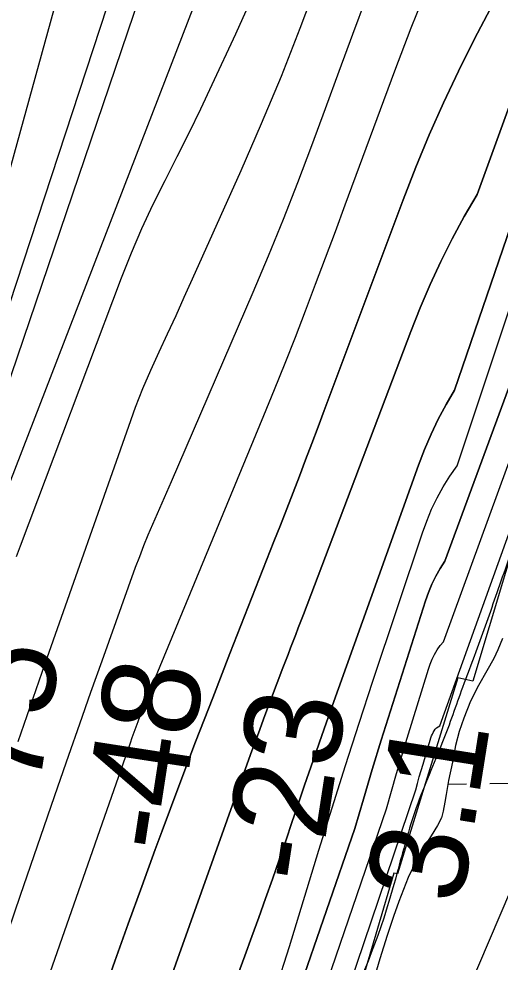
# Model space of a CAD drawing. Extents: x 3807117 to 3845308, y 337856 to 363736.
# Drawn here: x 3833182 to 3833513, y 344120 to 344768 of the extents above; entities that cross this region are included whole.
import ezdxf

# ---------------------------------------------------------------- set-up
doc = ezdxf.new("R2010")
doc.units = 0
for name, color, linetype in [('V-RIVR-EDGE', 7, 'Continuous'), ('V-RIVR-RANG', 7, 'Continuous'), ('V-RRAP-RVMT', 7, 'Continuous'), ('V-TOPO-DPTH', 7, 'Continuous'), ('V-TOPO-MAJR', 7, 'Continuous'), ('V-TOPO-MINR', 7, 'Continuous'), ('V-TOPO-WATR', 7, 'Continuous'), ('V-WETL-SWMP', 7, 'Continuous')]:
    doc.layers.add(name, color=color, linetype=linetype)

msp = doc.modelspace()

# ---------------------------------------------------------------- linework, layer by layer
at = {"layer": 'V-RIVR-EDGE'}
msp.add_spline([(3833993.63, 346073.15), (3834014.82, 346049.13), (3834027.93, 346045.03), (3834044.2, 346044.54), (3834056.42, 346046.77), (3834063.2, 346046.75), (3834065.46, 346045.39), (3834066.76, 346025.04), (3834070.78, 346004.68), (3834083.34, 345964.41), (3834083.78, 345960.79), (3834080.16, 345959.89), (3834071.58, 345963.98), (3834066.61, 345963.09), (3834057.1, 345958.14), (3834056.17, 345945.94), (3834053.89, 345939.61), (3834045.29, 345936.01), (3834032.17, 345933.79), (3834020.87, 345934.27), (3834010.46, 345930.67), (3833991.44, 345919.42), (3833968.34, 345903.65), (3833937.09, 345880.21), (3833918.03, 345855.85), (3833899.87, 345825.6), (3833887.57, 345788.55), (3833879.36, 345756.47), (3833874.27, 345710.36), (3833869.21, 345675.1), (3833852.34, 345618.62), (3833845.48, 345588.35), (3833842.69, 345557.15), (3833837.61, 345515.12), (3833834.32, 345463.13), (3833833.31, 345422.89), (3833835.49, 345389.87), (3833826.75, 345327.5), (3833812.58, 345266.04), (3833811.6, 345236.2), (3833805.63, 345198.23), (3833800.11, 345162.07), (3833798.68, 345131.78), (3833801.81, 345114.59), (3833810.79, 345092.41), (3833826.56, 345068.41), (3833838.72, 345048.94), (3833853.17, 345041.22), (3833864.45, 345032.14), (3833872.11, 345019.46), (3833872.08, 345008.16), (3833866.05, 344947.59), (3833859.08, 344872.55), (3833858.17, 344868.03), (3833853.65, 344868.04), (3833833.32, 344878.03), (3833815.73, 344894.81), (3833804.91, 344906.14), (3833797.68, 344908.87), (3833783.21, 344908.45), (3833736.6, 344893.2), (3833706.24, 344865.69), (3833687.65, 344845.39), (3833676.3, 344827.33), (3833665.38, 344800.68), (3833650.83, 344767.71), (3833632.62, 344715.75), (3833615.31, 344663.8), (3833598.93, 344623.14), (3833579.38, 344582.5), (3833566.62, 344539.57), (3833556.59, 344505.69), (3833525.62, 344416.69), (3833510.59, 344373.77), (3833496.02, 344333.11), (3833486.92, 344308.72), (3833473.26, 344271.22), (3833455.06, 344226.05), (3833441.84, 344180.87), (3833432.72, 344150.15), (3833396.31, 344055.73), (3833377.19, 344001.07), (3833358.09, 343958.61), (3833345.37, 343934.23), (3833328.05, 343879.56), (3833312.99, 343821.72), (3833296.6, 343775.64), (3833286.11, 343739.5), (3833276.03, 343687.07), (3833267.36, 343654.99), (3833255.05, 343614.32), (3833253.24, 343609.33)], degree=3, dxfattribs=at)
at = {"layer": 'V-RRAP-RVMT'}
for p, q in [((3833534.42, 344447.64), (3833494.04, 344313.06)), ((3833483.68, 344315.31), (3833442.17, 344180.65)), ((3833494.04, 344313.06), (3833483.68, 344315.31)), ((3833439.78, 344181.06), (3833400.57, 344049.13)), ((3833442.17, 344180.65), (3833439.78, 344181.06))]:
    msp.add_line(p, q, dxfattribs=at)
at = {"layer": 'V-TOPO-DPTH'}
for points in [[(3833630.63, 345014.55), (3833496.97, 344647.56), (3833488.19, 344632.52), (3833479.82, 344617.21), (3833472.06, 344601.58), (3833464.66, 344585.79), (3833457.82, 344569.74), (3833451.35, 344553.54), (3833377.45, 344358.79), (3833375.71, 344354.21), (3833373.95, 344349.63), (3833372.19, 344345.05), (3833370.41, 344340.48), (3833368.64, 344335.91), (3833366.88, 344331.33), (3833365.13, 344326.75), (3833363.39, 344322.17), (3833351.02, 344289.49), (3833346.47, 344277.36), (3833341.97, 344265.21), (3833337.54, 344253.03), (3833333.17, 344240.83), (3833281.5, 344095.44)], [(3833281.5, 344095.44), (3833333.17, 344240.83), (3833337.54, 344253.03), (3833341.97, 344265.21), (3833346.47, 344277.36), (3833351.02, 344289.49), (3833363.39, 344322.17), (3833365.13, 344326.75), (3833366.88, 344331.33), (3833368.64, 344335.91), (3833370.41, 344340.48), (3833372.19, 344345.05), (3833373.95, 344349.63), (3833375.71, 344354.21), (3833377.45, 344358.79), (3833451.35, 344553.54), (3833457.82, 344569.74), (3833464.66, 344585.79), (3833472.06, 344601.58), (3833479.82, 344617.21), (3833488.19, 344632.52), (3833496.97, 344647.56), (3833630.63, 345014.55)], [(3833641.2, 345004.31), (3833528.64, 344650.91), (3833481.49, 344513.01), (3833475.6, 344503.21), (3833470.3, 344493.06), (3833465.34, 344482.75), (3833460.88, 344472.22), (3833456.75, 344461.53), (3833396.19, 344292.71), (3833390.13, 344275.66), (3833384.14, 344258.59), (3833378.25, 344241.48), (3833372.42, 344224.35), (3833369.8, 344216.57), (3833365.3, 344203.33), (3833360.74, 344190.1), (3833356.11, 344176.9), (3833351.42, 344163.72), (3833346.69, 344150.56), (3833341.95, 344137.39), (3833337.2, 344124.24), (3833332.43, 344111.08)], [(3833332.43, 344111.08), (3833337.2, 344124.24), (3833341.95, 344137.39), (3833346.69, 344150.56), (3833351.42, 344163.72), (3833356.11, 344176.9), (3833360.74, 344190.1), (3833365.3, 344203.33), (3833369.8, 344216.57), (3833372.42, 344224.35), (3833378.25, 344241.48), (3833384.14, 344258.59), (3833390.13, 344275.66), (3833396.19, 344292.71), (3833456.75, 344461.53), (3833460.88, 344472.22), (3833465.34, 344482.75), (3833470.3, 344493.06), (3833475.6, 344503.21), (3833481.49, 344513.01), (3833528.64, 344650.91), (3833641.2, 345004.31)], [(3833197.92, 343608.5), (3833199.25, 343612.47), (3833212.54, 343649.95), (3833226.73, 343687.09), (3833241.54, 343724.01), (3833256.88, 343760.72), (3833412.87, 344211.65), (3833418.77, 344231.94), (3833424.8, 344252.2), (3833431.01, 344272.41), (3833437.35, 344292.57), (3833461.53, 344368.26), (3833463.59, 344374.01), (3833465.89, 344379.64), (3833468.56, 344385.11), (3833471.48, 344390.47), (3833474.86, 344395.5), (3833657.06, 344889.85)], [(3833657.06, 344889.85), (3833474.86, 344395.5), (3833471.48, 344390.47), (3833468.56, 344385.11), (3833465.89, 344379.64), (3833463.59, 344374.01), (3833461.53, 344368.26), (3833437.35, 344292.57), (3833431.01, 344272.41), (3833424.8, 344252.2), (3833418.77, 344231.94), (3833412.87, 344211.65), (3833256.88, 343760.72), (3833241.54, 343724.01), (3833226.73, 343687.09), (3833212.54, 343649.95), (3833199.25, 343612.47), (3833197.92, 343608.5)], [(3833241.74, 343609.16), (3833454.72, 344238.22), (3833455.93, 344242.7), (3833457.17, 344247.16), (3833458.45, 344251.62), (3833459.77, 344256.06), (3833465.25, 344274.16), (3833465.68, 344275.42), (3833466.18, 344276.64), (3833466.78, 344277.82), (3833467.44, 344278.97), (3833468.24, 344280), (3833469.13, 344280.91), (3833470.18, 344281.64), (3833471.33, 344282.24), (3833688.78, 344887.19)], [(3833506.15, 344775.51), (3833494.99, 344754.1), (3833484.15, 344732.52), (3833473.88, 344710.67), (3833464.04, 344688.64), (3833454.82, 344666.33), (3833446.03, 344643.85), (3833391.79, 344499.05), (3833387.54, 344487.77), (3833383.28, 344476.49), (3833378.99, 344465.23), (3833374.67, 344453.98), (3833370.33, 344442.73), (3833365.97, 344431.49), (3833361.59, 344420.27), (3833357.19, 344409.04), (3833326.89, 344332.03), (3833315.05, 344301.65), (3833303.32, 344271.23), (3833291.78, 344240.73), (3833280.35, 344210.2), (3833275.55, 344197.26), (3833266.17, 344171.75), (3833256.88, 344146.21), (3833247.73, 344120.62), (3833238.68, 344094.99)], [(3833238.68, 344094.99), (3833247.73, 344120.62), (3833256.88, 344146.21), (3833266.17, 344171.75), (3833275.55, 344197.26), (3833280.35, 344210.2), (3833291.78, 344240.73), (3833303.32, 344271.23), (3833315.05, 344301.65), (3833326.89, 344332.03), (3833357.19, 344409.04), (3833361.59, 344420.27), (3833365.97, 344431.49), (3833370.33, 344442.73), (3833374.67, 344453.98), (3833378.99, 344465.23), (3833383.28, 344476.49), (3833387.54, 344487.77), (3833391.79, 344499.05), (3833446.03, 344643.85), (3833454.82, 344666.33), (3833464.04, 344688.64), (3833473.88, 344710.67), (3833484.15, 344732.52), (3833494.99, 344754.1), (3833506.15, 344775.51)]]:
    msp.add_lwpolyline(points, dxfattribs=at)
at = {"layer": 'V-TOPO-MAJR'}
for points in [[(3832927.56, 343604.45), (3832927.66, 343604.82), (3832933.45, 343625.49), (3833008.69, 343896.96), (3833026.75, 343964.06), (3833044.15, 344031.32), (3833060.54, 344098.83), (3833076.27, 344166.51), (3833098.81, 344266.91), (3833102.65, 344284.54), (3833106.34, 344302.2), (3833109.8, 344319.9), (3833113.11, 344337.64), (3833315.5, 344933.25)], [(3833185.55, 344062.33), (3833258.43, 344270.61), (3833259.72, 344274.27), (3833261.02, 344277.92), (3833262.33, 344281.57), (3833263.66, 344285.22), (3833267.48, 344295.67), (3833267.98, 344297), (3833268.48, 344298.33), (3833269.01, 344299.65), (3833269.55, 344300.96), (3833270.1, 344302.27), (3833270.64, 344303.58), (3833271.19, 344304.89), (3833271.73, 344306.2), (3833350.29, 344495.59), (3833357.65, 344513.56), (3833364.9, 344531.56), (3833371.98, 344549.63), (3833378.95, 344567.74), (3833385.82, 344585.89), (3833392.66, 344604.06), (3833399.45, 344622.24), (3833406.21, 344640.43), (3833440.3, 344732.6), (3833451.6, 344762.09), (3833463.34, 344791.4)]]:
    msp.add_lwpolyline(points, dxfattribs=at)
at = {"layer": 'V-TOPO-MINR'}
for points in [[(3832857.18, 343603.4), (3832871.29, 343647.42), (3832899.09, 343733.62), (3832927.1, 343819.74), (3832955.43, 343905.76), (3832983.97, 343991.71), (3833028.08, 344123.76), (3833034.62, 344143.67), (3833041.02, 344163.61), (3833047.23, 344183.62), (3833053.3, 344203.67), (3833056.11, 344213.14), (3833060.46, 344228.54), (3833064.5, 344244.02), (3833068.11, 344259.6), (3833071.42, 344275.26), (3833076.32, 344300.21), (3833076.93, 344303.45), (3833077.51, 344306.7), (3833078.04, 344309.96), (3833078.53, 344313.22), (3833399.11, 345475.89)], [(3833281.14, 343609.75), (3833542.81, 344222.6), (3833545.01, 344227.54), (3833547.78, 344232.04), (3833575.64, 344292.26), (3833849.9, 345478.81)], [(3832892.2, 343603.92), (3832893.56, 343607.9), (3832911.37, 343661.09), (3832928.72, 343714.42), (3832945.77, 343767.86), (3832949.37, 343779.34), (3832967.78, 343838.65), (3832985.89, 343898.05), (3833003.57, 343957.59), (3833020.96, 344017.21), (3833031.9, 344055.24), (3833043.26, 344096.41), (3833054, 344137.74), (3833063.82, 344179.3), (3833073.03, 344221.01), (3833086.5, 344285.37), (3833088.45, 344295.03), (3833090.3, 344304.7), (3833092.02, 344314.4), (3833093.64, 344324.11), (3833468.24, 345464.24)], [(3833281.5, 344095.44), (3833333.17, 344240.83), (3833337.54, 344253.03), (3833341.97, 344265.21), (3833346.47, 344277.36), (3833351.02, 344289.49), (3833363.39, 344322.17), (3833365.13, 344326.75), (3833366.88, 344331.33), (3833368.64, 344335.91), (3833370.41, 344340.48), (3833372.19, 344345.05), (3833373.95, 344349.63), (3833375.71, 344354.21), (3833377.45, 344358.79), (3833451.35, 344553.54), (3833457.82, 344569.74), (3833464.66, 344585.79), (3833472.06, 344601.58), (3833479.82, 344617.21), (3833488.19, 344632.52), (3833496.97, 344647.56), (3833630.63, 345014.55)], [(3833332.43, 344111.08), (3833337.2, 344124.24), (3833341.95, 344137.39), (3833346.69, 344150.56), (3833351.42, 344163.72), (3833356.11, 344176.9), (3833360.74, 344190.1), (3833365.3, 344203.33), (3833369.8, 344216.57), (3833372.42, 344224.35), (3833378.25, 344241.48), (3833384.14, 344258.59), (3833390.13, 344275.66), (3833396.19, 344292.71), (3833456.75, 344461.53), (3833460.88, 344472.22), (3833465.34, 344482.75), (3833470.3, 344493.06), (3833475.6, 344503.21), (3833481.49, 344513.01), (3833528.64, 344650.91), (3833641.2, 345004.31)], [(3833358.59, 344101.16), (3833367.96, 344130.66), (3833388.13, 344196.81), (3833397.15, 344225.97), (3833406.33, 344255.08), (3833415.73, 344284.12), (3833425.29, 344313.1), (3833459.35, 344414.97), (3833462.35, 344423.14), (3833465.66, 344431.17), (3833469.44, 344439), (3833473.53, 344446.68), (3833478.17, 344454.01), (3833483.23, 344461), (3833657.1, 344983)], [(3832948.39, 343604.76), (3832985.52, 343740.44), (3833010.48, 343833.17), (3833034.92, 343926.03), (3833058.59, 344019.1), (3833081.73, 344112.3), (3833113.77, 344243.67), (3833120.35, 344271.32), (3833126.72, 344299.02), (3833132.78, 344326.79), (3833138.63, 344354.61), (3833347.97, 344895.76)], [(3833197.92, 343608.5), (3833199.25, 343612.47), (3833212.54, 343649.95), (3833226.73, 343687.09), (3833241.54, 343724.01), (3833256.88, 343760.72), (3833412.87, 344211.65), (3833418.77, 344231.94), (3833424.8, 344252.2), (3833431.01, 344272.41), (3833437.35, 344292.57), (3833461.53, 344368.26), (3833463.59, 344374.01), (3833465.89, 344379.64), (3833468.56, 344385.11), (3833471.48, 344390.47), (3833474.86, 344395.5), (3833657.06, 344889.85)], [(3833223.3, 343608.88), (3833434.64, 344225.28), (3833438.02, 344237.46), (3833441.49, 344249.6), (3833445.08, 344261.72), (3833448.76, 344273.8), (3833463.47, 344321.32), (3833464.68, 344324.76), (3833466.05, 344328.13), (3833467.67, 344331.39), (3833469.45, 344334.57), (3833471.55, 344337.5), (3833473.9, 344340.17), (3833668.71, 344873.67)], [(3833180.13, 344398.63), (3833182.82, 344406.12), (3833252.37, 344590.41), (3833259.15, 344607.45), (3833266.33, 344624.3), (3833274.1, 344640.89), (3833282.26, 344657.31), (3833290.62, 344673.64), (3833298.83, 344690.04), (3833306.83, 344706.55), (3833314.68, 344723.13), (3833330.94, 344758.05), (3833346.32, 344792.34)], [(3833181.23, 344271.55), (3833187.36, 344289.46), (3833193.56, 344307.34), (3833199.8, 344325.2), (3833257.23, 344488.4), (3833262, 344501.34), (3833267.04, 344514.16), (3833272.46, 344526.83), (3833278.15, 344539.39), (3833284, 344551.89), (3833289.8, 344564.4), (3833295.52, 344576.96), (3833301.2, 344589.53), (3833334.65, 344664.19), (3833348.72, 344696.53), (3833362.32, 344729.07), (3833375.2, 344761.89), (3833387.61, 344794.91)], [(3833166.12, 344117.34), (3833182.76, 344165.83), (3833208.46, 344240.49), (3833215.96, 344262.15), (3833223.52, 344283.78), (3833231.17, 344305.38), (3833238.88, 344326.96), (3833262, 344391.32), (3833264.79, 344398.82), (3833267.69, 344406.28), (3833270.75, 344413.68), (3833273.91, 344421.03), (3833277.15, 344428.36), (3833280.37, 344435.69), (3833283.57, 344443.04), (3833286.75, 344450.39), (3833342.8, 344580.4), (3833353.37, 344605.44), (3833363.68, 344630.59), (3833373.61, 344655.9), (3833383.27, 344681.3), (3833392.72, 344706.8), (3833402.14, 344732.3), (3833411.51, 344757.82), (3833420.86, 344783.35)], [(3833238.68, 344094.99), (3833247.73, 344120.62), (3833256.88, 344146.21), (3833266.17, 344171.75), (3833275.55, 344197.26), (3833280.35, 344210.2), (3833291.78, 344240.73), (3833303.32, 344271.23), (3833315.05, 344301.65), (3833326.89, 344332.03), (3833357.19, 344409.04), (3833361.59, 344420.27), (3833365.97, 344431.49), (3833370.33, 344442.73), (3833374.67, 344453.98), (3833378.99, 344465.23), (3833383.28, 344476.49), (3833387.54, 344487.77), (3833391.79, 344499.05), (3833446.03, 344643.85), (3833454.82, 344666.33), (3833464.04, 344688.64), (3833473.88, 344710.67), (3833484.15, 344732.52), (3833494.99, 344754.1), (3833506.15, 344775.51)]]:
    msp.add_lwpolyline(points, dxfattribs=at)
at = {"layer": 'V-TOPO-WATR'}
msp.add_lwpolyline([(3833241.74, 343609.16), (3833454.72, 344238.22), (3833455.93, 344242.7), (3833457.17, 344247.16), (3833458.45, 344251.62), (3833459.77, 344256.06), (3833465.25, 344274.16), (3833465.68, 344275.42), (3833466.18, 344276.64), (3833466.78, 344277.82), (3833467.44, 344278.97), (3833468.24, 344280), (3833469.13, 344280.91), (3833470.18, 344281.64), (3833471.33, 344282.24), (3833688.78, 344887.19)], dxfattribs=at)
at = {"layer": 'V-WETL-SWMP'}
for p, q in [((3833514.5, 344342.38), (3833511.23, 344334.49)), ((3833511.23, 344334.49), (3833508.61, 344328.58)), ((3833508.61, 344328.58), (3833503.63, 344320.16)), ((3833503.63, 344320.16), (3833497.99, 344310.04)), ((3833497.99, 344310.04), (3833492.49, 344299.26)), ((3833492.49, 344299.26), (3833487.91, 344287.69)), ((3833487.91, 344287.69), (3833484.64, 344278.49)), ((3833484.64, 344278.49), (3833482.16, 344268.76)), ((3833482.16, 344268.76), (3833479.95, 344257.33)), ((3833479.95, 344257.33), (3833477.21, 344244.71)), ((3833477.21, 344244.71), (3833475.78, 344235.12)), ((3833476.83, 344242.17), (3833489.74, 344242.36)), ((3833505.74, 344242.6), (3833537.73, 344243.08)), ((3833475.78, 344235.12), (3833474.73, 344229.73)), ((3833474.73, 344229.73), (3833473.69, 344223.56)), ((3833473.69, 344223.56), (3833472.39, 344218.96)), ((3833472.39, 344218.96), (3833469.63, 344213.7)), ((3833469.63, 344213.7), (3833465.44, 344206.73)), ((3833465.44, 344206.73), (3833461.38, 344200.55)), ((3833461.38, 344200.55), (3833455.48, 344190.29)), ((3833455.48, 344190.29), (3833449.59, 344178.07)), ((3833449.59, 344178.07), (3833443.05, 344161.64)), ((3833443.05, 344161.64), (3833439.38, 344151.12)), ((3833439.38, 344151.12), (3833435.2, 344138.11)), ((3833435.2, 344138.11), (3833429.97, 344122.07)), ((3833429.97, 344122.07), (3833424.35, 344102.36))]:
    msp.add_line(p, q, dxfattribs=at)

# ---------------------------------------------------------------- texts
at = {"layer": 'V-RIVR-RANG'}
for s, rotation, p in [('-75', 81.23108, (3833190.71, 344207.6)), ('-48', 81.23108, (3833289.75, 344193.67)), ('-23', 81.23108, (3833387.65, 344172.45)), ('3.1', 80.94833, (3833486.26, 344158.42))]:
    msp.add_text(s, height=67, rotation=rotation, dxfattribs=at).set_placement(p)

doc.saveas('drawing.dxf')
